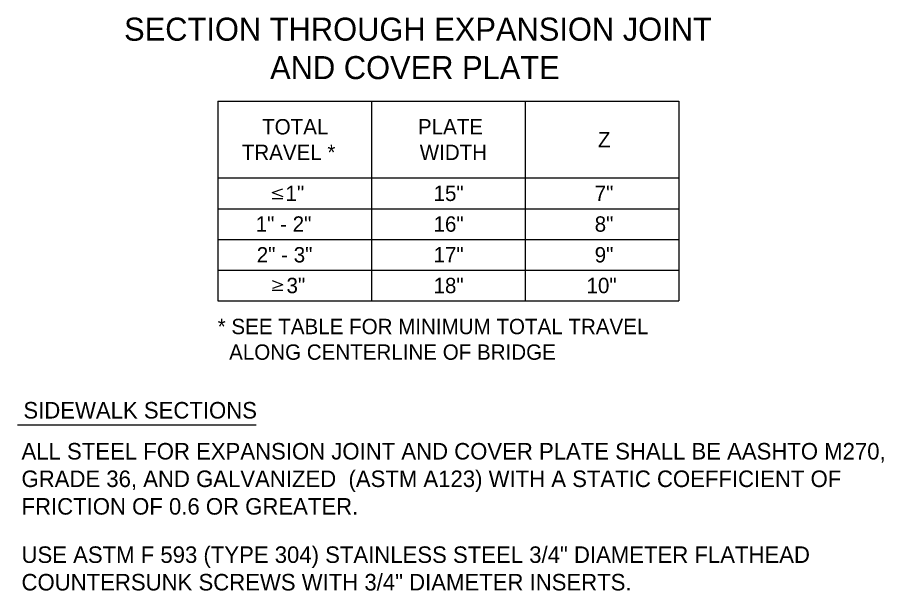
# Model space of a CAD drawing. Extents: x 19590 to 20151, y 19944 to 20103.
# Drawn here: x 19879.55 to 19905.61, y 20034.32 to 20051.58 of the extents above; entities that cross this region are included whole.
import ezdxf

# ---------------------------------------------------------------- set-up
doc = ezdxf.new("R2010")
doc.units = 0
doc.layers.add('DETAIL_TEXT_DIMEN_PR', color=7, linetype='Continuous')

msp = doc.modelspace()

# ---------------------------------------------------------------- linework, layer by layer
at = {"layer": 'DETAIL_TEXT_DIMEN_PR'}
for p, q in [((19885.574, 20049.061), (19885.574, 20043.048)), ((19885.574, 20049.061), (19899.449, 20049.061)), ((19885.574, 20049.061), (19885.574, 20043.048)), ((19885.574, 20049.061), (19899.449, 20049.061)), ((19890.199, 20049.061), (19890.199, 20043.048)), ((19890.199, 20049.061), (19890.199, 20043.048)), ((19894.824, 20049.061), (19894.824, 20043.048)), ((19894.824, 20049.061), (19894.824, 20043.048)), ((19899.449, 20049.061), (19899.449, 20043.048)), ((19899.449, 20049.061), (19899.449, 20043.048)), ((19885.574, 20046.748), (19899.449, 20046.748)), ((19885.574, 20046.748), (19899.449, 20046.748)), ((19887.214, 20046.309), (19887.529, 20046.424)), ((19887.214, 20046.309), (19887.529, 20046.424)), ((19887.214, 20046.309), (19887.529, 20046.195)), ((19887.214, 20046.309), (19887.529, 20046.195)), ((19887.214, 20046.132), (19887.538, 20046.132)), ((19887.214, 20046.132), (19887.538, 20046.132)), ((19885.574, 20045.823), (19899.449, 20045.823)), ((19885.574, 20045.823), (19899.449, 20045.823)), ((19885.574, 20044.898), (19899.449, 20044.898)), ((19885.574, 20044.898), (19899.449, 20044.898)), ((19885.574, 20043.973), (19899.449, 20043.973)), ((19885.574, 20043.973), (19899.449, 20043.973)), ((19887.538, 20043.534), (19887.223, 20043.649)), ((19887.538, 20043.534), (19887.223, 20043.649)), ((19887.538, 20043.534), (19887.223, 20043.42)), ((19887.538, 20043.534), (19887.223, 20043.42)), ((19887.538, 20043.357), (19887.214, 20043.357)), ((19887.538, 20043.357), (19887.214, 20043.357)), ((19885.574, 20043.048), (19899.449, 20043.048)), ((19885.574, 20043.048), (19899.449, 20043.048)), ((19879.547, 20039.315), (19886.729, 20039.315)), ((19879.547, 20039.315), (19886.729, 20039.315))]:
    msp.add_line(p, q, dxfattribs=at)

# ---------------------------------------------------------------- texts
for s, height, p in [('SECTION THROUGH EXPANSION JOINT', 0.69385, (19882.758, 20050.88)), ('SECTION THROUGH EXPANSION JOINT', 0.69385, (19882.758, 20050.88)), ('AND COVER PLATE', 0.69385, (19887.151, 20049.724)), ('AND COVER PLATE', 0.69385, (19887.151, 20049.724)), ('* SEE TABLE FOR MINIMUM TOTAL TRAVEL ', 0.4625, (19885.574, 20042.046)), ('* SEE TABLE FOR MINIMUM TOTAL TRAVEL ', 0.4625, (19885.574, 20042.046)), ('  ALONG CENTERLINE OF BRIDGE', 0.4625, (19885.574, 20041.275)), ('  ALONG CENTERLINE OF BRIDGE', 0.4625, (19885.574, 20041.275)), ('ALL STEEL FOR EXPANSION JOINT AND COVER PLATE SHALL BE AASHTO M270, ', 0.4976, (19879.673, 20038.273)), ('ALL STEEL FOR EXPANSION JOINT AND COVER PLATE SHALL BE AASHTO M270, ', 0.4976, (19879.673, 20038.273)), ('GRADE 36, AND GALVANIZED  (ASTM A123) WITH A STATIC COEFFICIENT OF ', 0.4976, (19879.673, 20037.444)), ('GRADE 36, AND GALVANIZED  (ASTM A123) WITH A STATIC COEFFICIENT OF ', 0.4976, (19879.673, 20037.444)), ('FRICTION OF 0.6 OR GREATER.', 0.4976, (19879.673, 20036.614)), ('FRICTION OF 0.6 OR GREATER.', 0.4976, (19879.673, 20036.614)), ('USE ASTM F 593 (TYPE 304) STAINLESS STEEL 3/4" DIAMETER FLATHEAD ', 0.4976, (19879.673, 20035.16)), ('USE ASTM F 593 (TYPE 304) STAINLESS STEEL 3/4" DIAMETER FLATHEAD ', 0.4976, (19879.673, 20035.16)), ('COUNTERSUNK SCREWS WITH 3/4" DIAMETER INSERTS.', 0.4976, (19879.673, 20034.331)), ('COUNTERSUNK SCREWS WITH 3/4" DIAMETER INSERTS.', 0.4976, (19879.673, 20034.331))]:
    msp.add_text(s, height=height, dxfattribs=at).set_placement(p)
for s, height, p in [('TOTAL', 0.4625, (19886.91, 20048.059)), ('TOTAL', 0.4625, (19886.91, 20048.059)), ('PLATE', 0.4625, (19891.597, 20048.059)), ('PLATE', 0.4625, (19891.597, 20048.059)), ('Z', 0.462, (19897.015, 20047.673)), ('Z', 0.462, (19897.015, 20047.673)), ('TRAVEL *', 0.4625, (19886.298, 20047.288)), ('TRAVEL *', 0.4625, (19886.298, 20047.288)), ('WIDTH', 0.4625, (19891.651, 20047.288)), ('WIDTH', 0.4625, (19891.651, 20047.288)), (' 1"', 0.4625, (19887.442, 20046.055)), (' 1"', 0.4625, (19887.442, 20046.055)), ('15"', 0.4625, (19892.067, 20046.055)), ('15"', 0.4625, (19892.067, 20046.055)), ('7"', 0.4625, (19896.915, 20046.055)), ('7"', 0.4625, (19896.915, 20046.055)), ('1" - 2"', 0.4625, (19886.717, 20045.13)), ('1" - 2"', 0.4625, (19886.717, 20045.13)), ('16"', 0.4625, (19892.067, 20045.13)), ('16"', 0.4625, (19892.067, 20045.13)), ('8"', 0.4625, (19896.915, 20045.13)), ('8"', 0.4625, (19896.915, 20045.13)), ('2" - 3"', 0.4625, (19886.748, 20044.205)), ('2" - 3"', 0.4625, (19886.748, 20044.205)), ('17"', 0.4625, (19892.067, 20044.205)), ('17"', 0.4625, (19892.067, 20044.205)), ('9"', 0.4625, (19896.915, 20044.205)), ('9"', 0.4625, (19896.915, 20044.205)), (' 3"', 0.4625, (19887.472, 20043.28)), (' 3"', 0.4625, (19887.472, 20043.28)), ('18"', 0.4625, (19892.067, 20043.28)), ('18"', 0.4625, (19892.067, 20043.28)), ('10"', 0.4625, (19896.669, 20043.28)), ('10"', 0.4625, (19896.669, 20043.28)), ('SIDEWALK SECTIONS', 0.4976, (19879.73, 20039.507)), ('SIDEWALK SECTIONS', 0.4976, (19879.73, 20039.507))]:
    msp.add_text(s, height=height, rotation=0, dxfattribs=at).set_placement(p)

doc.saveas('drawing.dxf')
